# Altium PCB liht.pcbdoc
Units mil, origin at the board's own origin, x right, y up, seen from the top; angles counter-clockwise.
Board outline 7874 x 3937 mil, 2 copper layers (Top Layer, Bottom Layer); 134 components, 84 nets, 415 pads, 109 vias.
Unrouted connection lines stored in the file: 3.
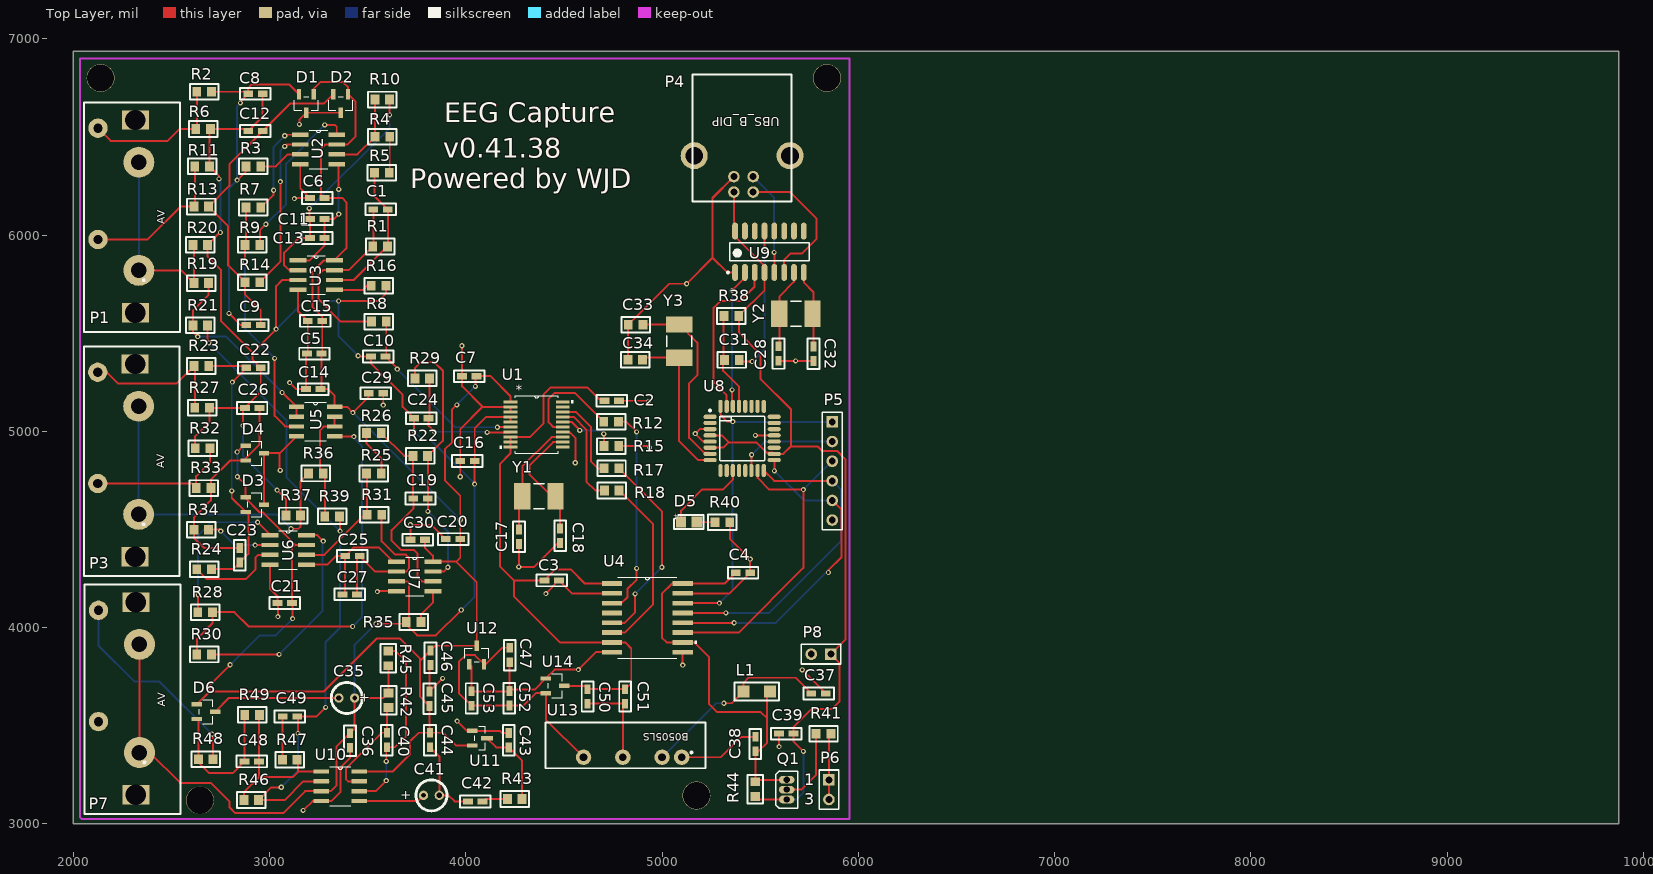
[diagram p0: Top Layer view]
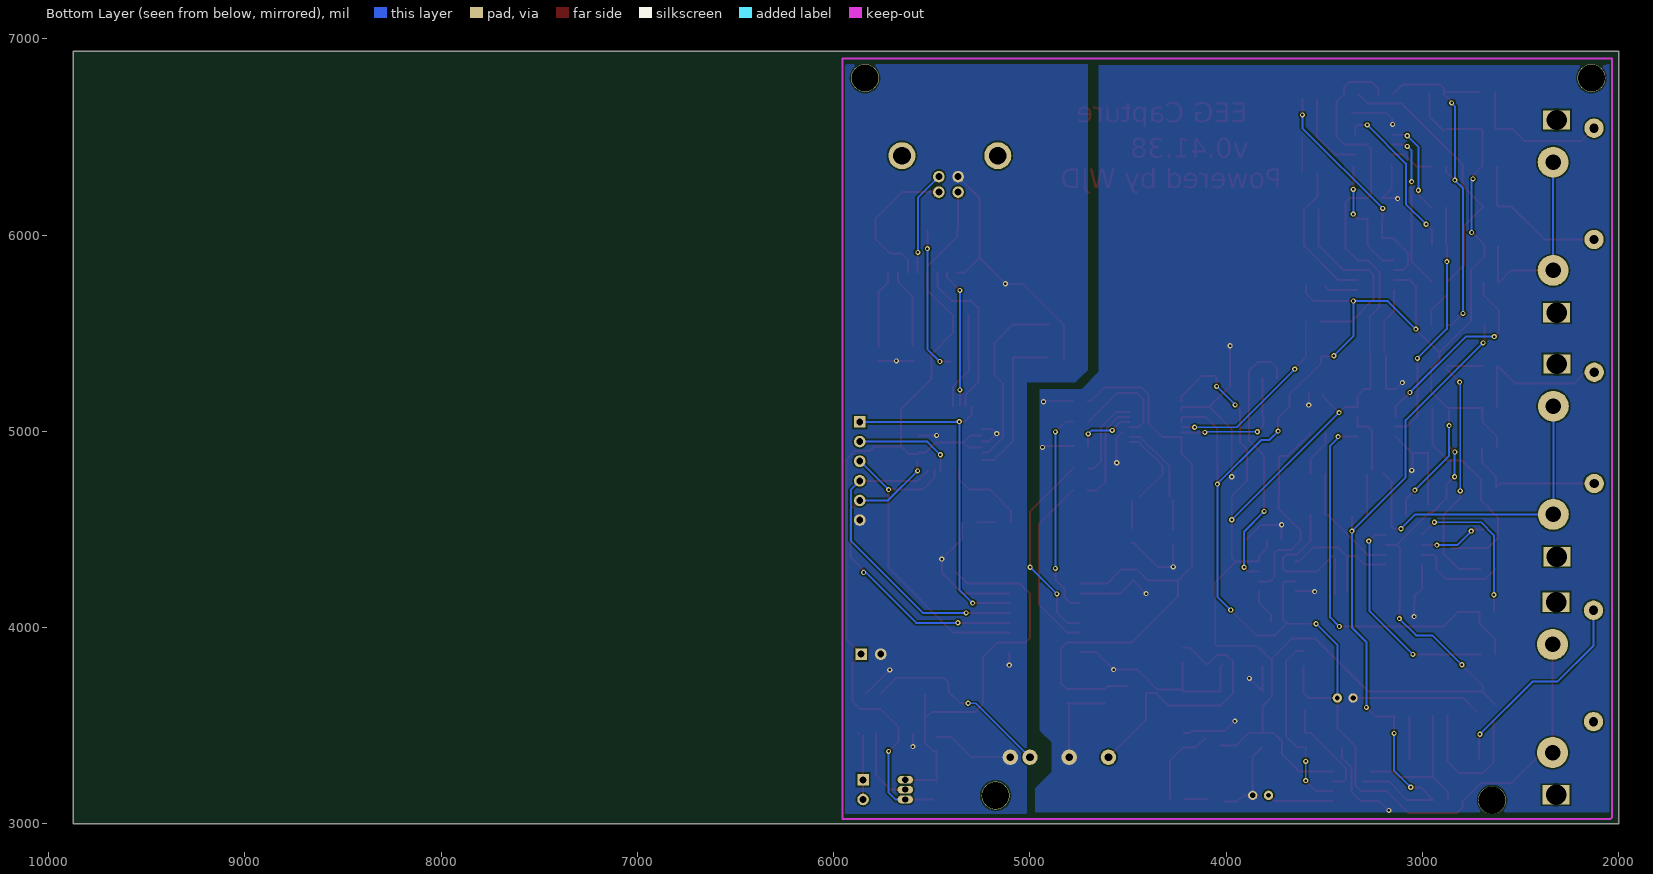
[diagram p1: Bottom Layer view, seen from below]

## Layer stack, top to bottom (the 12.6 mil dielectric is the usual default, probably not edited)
Top Layer: signal copper 1.4
Dielectric: dielectric 12.6, FR-4, Dk 4.8
Bottom Layer: signal copper 1.4

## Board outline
2000,3000 9874,3000 9874,6937 2000,6937

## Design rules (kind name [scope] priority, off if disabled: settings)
Clearance [All] p1: gap=8
PolygonConnect [All] p1: connectstyle=Direct reliefconductorwidth=10 reliefentries=4 polygonreliefangle="90 Angle" airgapwidth=10
RoutingVias [All] p1: holewidth=12 width=24 viastyle="Through Hole" minholewidth=12 minwidth=24 maxholewidth=28 maxwidth=50
SolderMaskExpansion [All] p1: expansion=4
Width [All] p1: maxlimit=10 minlimit=8 preferedwidth=10
28 further rules are at their usual default settings.

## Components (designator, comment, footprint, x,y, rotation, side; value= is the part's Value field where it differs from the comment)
C1 "Cap" 0603 3539,6131 r0 top
C2 "Cap" 0603 4717,5156 r0 top
C3 "Cap" 0603 4465,4241 r180 top
C4 "Cap" 0603 5385,4280 r0 top
C5 "Cap" 0603 3202,5396 r0 top
C6 "Cap" 0603 3216,6189 r0 top
C7 "Cap" 0603 3991,5281 r0 top
C8 "Cap" 0603 2956,6720 r180 top
C9 "Cap" 0603 2946,5541 r180 top
C10 "Cap" 0603 3581,5382 r180 top
C11 "Cap" 0603 3216,6081 r0 top
C12 "Cap" 0603 2956,6530 r180 top
C13 "Cap" 0603 3216,5985 r0 top
C14 "Cap" 0603 3196,5215 r0 top
C15 "Cap" 0603 3205,5563 r0 top
C16 "Cap" 0603 4036,4849 r180 top
C17 "Cap" 0603 4271,4491 r270 top
C18 "Cap" 0603 4481,4495 r270 top
C19 "Cap" 0603 3797,4658 r180 top
C20 "Cap" 0603 3908,4451 r0 top
C21 "Cap" 0603 3051,4126 r0 top
C22 "Cap" 0603 2946,5324 r180 top
C23 "Cap" 0603 2849,4396 r270 top
C24 "Cap" 0603 3801,5067 r180 top
C25 "Cap" 0603 3450,4365 r180 top
C26 "Cap" 0603 2939,5119 r180 top
C27 "Cap" 0603 3436,4170 r180 top
C28 "Cap" 0603 5593,5424 r270 top
C29 "Cap" 0603 3570,5194 r180 top
C30 "Cap" 0603 3728,4448 r0 top
C31 "Cap" 0805 5393,5364 r180 top
C32 "Cap" 0603 5771,5423 r270 top
C33 "Cap" 0805 4828,5543 r0 top
C34 "Cap" 0805 4826,5365 r0 top
C35 "Cap Pol2" 47uf 3394,3642 r180 top
C36 "Cap" 0603 3410,3452 r270 top
C37 "Cap" 0603 5770,3665 r0 top
C38 "Cap" 0603 5475,3380 r90 top
C39 "Cap" 0603 5660,3460 r180 top
C40 "Cap" 0603 3598,3455 r270 top
C41 "Cap Pol2" 47uf 3825,3146 r0 top
C42 "Cap" 0603 4076,3115 r180 top
C43 "Cap" 0603 4219,3400 r90 top
C44 "Cap" 0603 3818,3455 r270 top
C45 "Cap" 0603 3815,3611 r90 top
C46 "Cap" 0603 3820,3874 r270 top
C47 "Cap" 0603 4224,3888 r270 top
C48 "Cap" 0603 2937,3319 r180 top
C49 "Cap" 0603 3132,3547 r180 top
C50 "Cap" 0603 4621,3677 r270 top
C51 "Cap" 0603 4812,3677 r270 top
C52 "Cap" 0603 4222,3614 r90 top
C53 "Cap" 0603 4030,3612 r90 top
D1 "BAV99" SOT23 3188,6670 r180 top
D2 "BAV99" SOT23 3363,6670 r180 top
D3 "BAV99" SOT23 2926,4627 r270 top
D4 "BAV99" SOT23 2926,4889 r270 top
D5 "LED_R" 0805_极性 5137,4538 r0 top
D6 "BAV99" SOT23 2677,3572 r270 top
L1 "Inductor" 1206 5415,3675 r0 top
P1 "Header 3" AV 2335,5820 r90 top
P3 "Header 3" AV 2334,4577 r90 top
P4 "USB" USB_B_DIP 5652,6809 r180 top
P5 "Header 6" HDR1X6 5867,5048 r270 top
P6 "Header 2" HDR1X2 5850,3225 r270 top
P7 "Header 3" AV 2338,3364 r90 top
P8 "Header 2" HDR1X2 5860,3865 r180 top
Q1 "MOSFET-P" E3 5635,3175 r0 top
R1 "Res2" 0805 3526,5942 r0 top
R2 "Res2" 0805 2705,6730 r180 top
R3 "Res2" 0805 2956,6350 r180 top
R4 "Res2" 0805 3613,6501 r180 top
R5 "Res2" 0805 3535,6317 r0 top
R6 "Res2" 0805 2700,6540 r180 top
R7 "Res2" 0805 2956,6140 r180 top
R8 "Res2" 0805 3595,5559 r180 top
R9 "Res2" 0805 2951,5950 r180 top
R10 "Res2" 0805 3537,6690 r0 top
R11 "Res2" 0805 2620,6350 r0 top
R12 "Res2" 0805 4778,5049 r180 top
R13 "Res2" 0805 2690,6145 r180 top
R14 "Res2" 0805 2951,5760 r180 top
R15 "Res2" 0805 4779,4925 r180 top
R16 "Res2" 0805 3519,5742 r0 top
R17 "Res2" 0805 4780,4812 r180 top
R18 "Res2" 0805 4781,4699 r180 top
R19 "Res2" 0805 2690,5755 r180 top
R20 "Res2" 0805 2610,5950 r0 top
R21 "Res2" 0805 2610,5540 r0 top
R22 "Res2" 0805 3806,4875 r180 top
R23 "Res2" 0805 2691,5333 r180 top
R24 "Res2" 0805 2630,4298 r0 top
R25 "Res2" 0805 3570,4785 r180 top
R26 "Res2" 0805 3570,4991 r180 top
R27 "Res2" 0805 2695,5120 r180 top
R28 "Res2" 0805 2635,4079 r0 top
R29 "Res2" 0805 3816,5270 r180 top
R30 "Res2" 0805 2705,3864 r180 top
R31 "Res2" 0805 3497,4575 r0 top
R32 "Res2" 0805 2697,4914 r180 top
R33 "Res2" 0805 2702,4711 r180 top
R34 "Res2" 0805 2690,4499 r180 top
R35 "Res2" 0805 3772,4029 r180 top
R36 "Res2" 0805 3274,4786 r180 top
R37 "Res2" 0805 3159,4571 r180 top
R38 "Res2" 0805 5316,5588 r0 top
R39 "Res2" 0805 3282,4567 r0 top
R40 "Res2" 0805 5270,4537 r0 top
R41 "Res2" 0805 5860,3460 r180 top
R42 "Res2" 0805 3607,3593 r90 top
R43 "Res2" 0805 4287,3127 r180 top
R44 "Res2" 0805 5475,3140 r90 top
R45 "Res2" 0805 3605,3881 r270 top
R46 "Res2" 0805 2945,3122 r180 top
R47 "Res2" 0805 3066,3327 r0 top
R48 "Res2" 0805 2638,3330 r0 top
R49 "Res2" 0805 2949,3556 r180 top
U1 "ADS1255" ADS1255 4361,5035 r0 top
U2 "AD620" AD620 3250,6436 r0 top
U3 "AD8606" AD8606 3238,5796 r0 top
U4 "ADUM1402BRWZ" ADUM1402BRWZ 4925,4050 r0 top
U5 "OPA2335" OPA2335 3235,5050 r0 top
U6 "AD620" AD620 3095,4396 r0 top
U7 "AD8606" AD8606 3740,4261 r0 top
U8 "ATmega328P-AU" TQFP_32_短PIN 5408,4964 r0 top
U9 "CH340G" SOP_16 5547,5915 r90 top
U10 "OPA2335" OPA2335 3361,3192 r0 top
U11 "REF3125AIDBZT" REF3125 4073,3437 r270 top
U12 "MCP1703-5002" SOT23 4056,3861 r0 top
U13 "B1205_0505" B0505LS 5100,3340 r180 top
U14 "MCP1703-3002" SOT23 4455,3704 r270 top
Y1 "8M" XTAL_5023 4373,4669 r180 top
Y2 "XTAL" XTAL_5032_2PIN 5682,5599 r180 top
Y3 "XTAL" XTAL_5032_2PIN 5087,5460 r270 top

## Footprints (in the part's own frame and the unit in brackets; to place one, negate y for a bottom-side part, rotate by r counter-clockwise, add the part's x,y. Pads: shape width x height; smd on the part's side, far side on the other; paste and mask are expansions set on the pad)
47uf [mm]
  round 1.2 hole 0.6: 1(-1.02,0)
  round 1.2 hole 0.7: 2(1.02,0)
  silkscreen extent -2.01,-2.01 2.01,2.01
0603 [mil]
  rect 50x31 smd: 1(-9.84,0) 2(64,0)
  silkscreen extent -50,-30 105,30
0805 [mil]
  rect 45x50 smd: 1(0,0) 2(75,0)
  silkscreen extent -35,-40 110,40
0805_极性 [mm]
  rect 1.35x1.4 smd: 1(-1.025,0) 2(1.025,0)
  silkscreen extent -1.91,-0.89 1.91,0.89, body extent -1,-0.64 1,0.64, height 1.25
1206 [mil]
  rect 60x63 smd: 1(0,0) 2(135,0)
  silkscreen extent -45,-45 180,45
AD620 [mil]
  rect 86x22 smd: 1(-93,75) 2(-93,25) 3(-93,-25) 4(-93,-75) 5(93,-75) 6(93,-25) 7(93,25) 8(93,75)
  silkscreen extent -46,-98 46,98
AD8606 [mil]
  rect 86x22 smd: 1(-93,75) 2(-93,25) 3(-93,-25) 4(-93,-75) 5(93,-75) 6(93,-25) 7(93,25) 8(93,75)
  silkscreen extent -46,-98 46,98
ADS1255 [mil]
  rect 69x15 smd: 1(-133,115.16) 2(-133,89.57) 3(-133,63.98) 4(-133,38.39) 5(-133,12.8) 6(-133,-12.8) 7(-133,-38.39) 8(-133,-63.98) 9(-133,-89.57) 10(-133,-115.16) 11(133,-115.16) 12(133,-89.57) 13(133,-63.98) 14(133,-38.39) 15(133,-12.8) 16(133,12.8) 17(133,38.39) 18(133,63.98) 19(133,89.57) 20(133,115.16)
  silkscreen extent -188,-148 188,148
ADUM1402BRWZ [mil]
  rect 102.5x24 smd: 1(-180.25,175) 2(-180.25,125) 3(-180.25,75) 4(-180.25,25) 5(-180.25,-25) 6(-180.25,-75) 7(-180.25,-125) 8(-180.25,-175) 9(180.25,-175) 10(180.25,-125) 11(180.25,-75) 12(180.25,-25) 13(180.25,25) 14(180.25,75) 15(180.25,125) 16(180.25,175)
  silkscreen extent -150,-206 252,206
AV [mm]
  rect 2.5x3.5 hole 2.64: 0(-5.46,0.457) 0(19.46,0.457)
  round 2.5 hole 1.2: 1(4,5.3) 3(18.4,5.3)
  round 4 hole 2: 2(0,0) 2(14,0)
  silkscreen extent -7.98,-5.31 21.74,7.09
B0505LS [mm]
  round 2 hole 1: 1(0,0) 2(2.54,0) 3(7.62,0) 4(12.7,0)
  silkscreen extent -3.07,-4.5 17.6,1.42
E3 [mm] "TO, Flat Index; 3 In-Line, Axial Leads; Body Dia. 4.6mm; Lead Dia. 0.5 mm (max)"
  oval 2x1 hole 0.8: 1(0,1.27) 2(0,0) 3(0,-1.27)
  silkscreen extent -1.41,-2.41 1.41,2.41
HDR1X2 [mm] "Connector; Header; 2 Position"
  rect 1.5x1.5 hole 0.9: 1(0,0)
  round 1.5 hole 0.9: 2(2.54,0)
  silkscreen extent -1.27,-1.27 3.81,1.27
HDR1X6 [mm] "Connector; Header; 6 Position"
  rect 1.5x1.5 hole 0.9: 1(0,0)
  round 1.5 hole 0.9: 2(2.54,0) 3(5.08,0) 4(7.62,0) 5(10.16,0) 6(12.7,0)
  silkscreen extent -1.27,-1.27 13.97,1.27
OPA2335 [mil]
  rect 78x22 smd: 1(-97,75) 2(-97,25) 3(-97,-25) 4(-97,-75) 5(97,-75) 6(97,-25) 7(97,25) 8(97,75)
  silkscreen extent -54,-98 54,98
REF3125 [mil] "SOP 16"
  rect 22x52 smd: 1(-37.4,-40) 2(37.4,-40)
  rect 22x62.5 smd: 3(0,34.75)
  silkscreen extent -60,-28 60,28
SOP_16 [mm] "SOP 16"
  oval 2.2x0.75 smd: 1(-2.675,4.445) 2(-2.675,3.175) 3(-2.675,1.905) 4(-2.675,0.635) 5(-2.675,-0.635) 6(-2.675,-1.905) 7(-2.675,-3.175) 8(-2.675,-4.445) 9(2.675,-4.445) 10(2.675,-3.175) 11(2.675,-1.905) 12(2.675,-0.635) 13(2.675,0.635) 14(2.675,1.905) 15(2.675,3.175) 16(2.675,4.445)
  silkscreen extent -2.8,-5.15 1.17,5.49, body extent -2.1,-5.15 2.1,5.15, height 1.7
SOT23 [mil]
  rect 22x52 smd: 1(-37.4,-47.06) 2(37.4,-47.06) 3(0,47.06)
  silkscreen extent -61,-35 61,35
TQFP_32_短PIN [mm]
  oval 1.7x0.55 smd: 1(-4.15,2.8) 2(-4.15,2) 3(-4.15,1.2) 4(-4.15,0.4) 5(-4.15,-0.4) 6(-4.15,-1.2) 7(-4.15,-2) 8(-4.15,-2.8) 17(4.15,-2.8) 18(4.15,-2) 19(4.15,-1.2) 20(4.15,-0.4) 21(4.15,0.4) 22(4.15,1.2) 23(4.15,2) 24(4.15,2.8)
  oval 0.55x1.7 smd: 9(-2.8,-4.15) 10(-2,-4.15) 11(-1.2,-4.15) 12(-0.4,-4.15) 13(0.4,-4.15) 14(1.2,-4.15) 15(2,-4.15) 16(2.8,-4.15) 25(2.8,4.15) 26(2,4.15) 27(1.2,4.15) 28(0.4,4.15) 29(-0.4,4.15) 30(-1.2,4.15) 31(-2,4.15) 32(-2.8,4.15)
  silkscreen extent -4.27,-2.9 2.9,3.75, body extent -3.5,-3.5 3.5,3.5, height 1.2
USB_B_DIP [mm]
  round 3.5 hole 2.3: 0(0,10.28) 0(12.4,10.28)
  round 1.5 hole 0.92: 1(7.27,14.99) 2(4.77,14.99) 3(4.77,12.99) 4(7.27,12.99)
  silkscreen extent -0.2,-0.2 12.6,16.21
XTAL_5023 [mm] "5032_CPX_53GB"
  rect 2.1x3.45 smd: 1(-2.15,0) 2(2.15,0)
  silkscreen extent -0.7,-1.63 0.7,1.63, body extent -2.58,-1.68 2.57,1.68, height 1.25
XTAL_5032_2PIN [mm] "5032_CPX_53GB"
  rect 2.1x3.45 smd: 1(-2.15,0) 2(2.15,0)
  silkscreen extent -0.7,-1.63 0.7,1.63, body extent -2.58,-1.68 2.57,1.68, height 1.25

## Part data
C1 C2 C3 C4 C5 C6 C7 C8 C9 C10 C11 C12 C13 C14 C15 C16 C17 C18 C19 C20 C21 C22 C23 C24 C25 C26 C27 C28 C29 C30 C31 C32 C33 C34 C36 C37 C38 C39 C40 C42 C43 C44 C45 C46 C47 C48 C49 C50 C51 C52 C53: "Capacitor"
C35 C41: "Polarized Capacitor (Axial)"
D5: library part LED
P1 P3 P7: "Header, 3-Pin"
P5: "Header, 6-Pin"
P6 P8: "Header, 2-Pin"
Q1: "P-Channel MOSFET"
R38 R40: "Resistor"
U8: "8-bit AVR Microcontroller, 32KB Flash, 1KB EEPROM, 2KB SRAM, 32-pin TQFP, Industrial Grade (-40癈 to 85癈)"
U13: library part B1205/B0505
Y1: library part XTAL, "Crystal Oscillator"
Y2 Y3: "Crystal Oscillator"

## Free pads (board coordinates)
  round 141.73 hole 137.8: 0(5175,3145) 1(2646,3121) 2(5840,6800) 3(2140,6800)

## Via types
v1: diameter 26, hole 13, Top Layer to Bottom Layer, 109 vias

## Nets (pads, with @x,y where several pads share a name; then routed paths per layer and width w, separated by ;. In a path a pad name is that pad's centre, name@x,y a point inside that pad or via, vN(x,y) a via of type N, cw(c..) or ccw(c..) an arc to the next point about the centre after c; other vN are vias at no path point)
+3V: C2.1 C3.2 C50.1 C51.1 U1.8 U1.9 U1.10 U4.1 U4.7 U14.3 | length 3358.8
  Top Layer w10: U14.3 4603.84,3704 C50.1 C51.1 4843,3717.84 4843,3894 4812,3925 U4.7 4480,3925 4245,4160 4245,4241 ; C2.1 4688,5156 4620,5224 4432,5224 4397,5189 4397,5041 4327.02,4971.02 U1.8 U1.9 U1.10 4228,4888 4175,4835 4175,4311 4245,4241 ; U4.1 4606,4225 4534,4297 4457,4297 C3.2 4245,4241
+5V_SW: C4.1 C38.1 L1.2 Q1.1 R44.2 U4.10 U4.16 | length 2119.7
  Top Layer w10: C4.1 5320.16,4225 U4.16 5052,4225 4999,4172 4999,3949 5023,3925 U4.10 5165,3925 5240,3850 5240,3610 5280,3570 5502.5,3570 5535,3537.5 ; R44.2 C38.1 5490.16,3370.16 5535,3415 5535,3537.5 ; R44.2@5485,3225 Q1.1 ; L1.2@5535,3660 5535,3537.5
+5V_USB: C39.1 P4.1 P8.1 Q1.3 R38.2 R44.1 U8.4 U8.6 U8.18 U9.4 U9.16 | length 4533.4
  Top Layer w10: U8.6 5311.76,4916.76 5339.5,4944.5 ; U8.4 5304.25,4979.75 5339.5,4944.5 ; U9.16@5365.78,6026.54 P4.1 ; U9.16 5372,5991 U9.4@5522,5841 ; R44.1@5490,3125 Q1.3 ; U9.4 5522,5719 R38.2 5391,5504 5501,5394 5501,5269 5656,5114 5656,4923 ; v1(5720,3370) 5669.84,3420.16 C39.1 5669.84,3494.84 5760,3585 5865,3585 5905,3625 5905,3820 P8.1 5934,3939 5934,4858 5892,4900 5815,4900 5792,4923 5656,4923 ; 5339.5,4944.5 5340,4944 5479,4944 5530.07,4892.93 5563.72,4892.93 U8.18 5618.26,4885.26 5656,4923
  Bottom Layer w10: Q1.3 5685,3125 5720,3160 v1(5720,3370)
+5VA: C5.2 C6.2 C7.2 C14.2 C15.2 C20.2 C21.2 C29.2 C30.2 C44.1 C45.1 C46.1 D1.1 D2.1 D3.1 D4.1 D6.1 U1.1 U2.7 U3.8 U5.8 U6.7 U7.8 U10.8 U11.2 U12.3 | length 9740.8
  Top Layer w10: D6.1 2695.54,3675 ; v1(2800,3811) 2695.54,3706.54 2695.54,3675 ; v1(2835,4895) D4.1@2866.4,4926.4 ; v1(2837,4769) 2878.94,4727.06 D3.1 2878.94,4659.06 2952,4586 2969,4586 3134,4421 U6.7 ; C21.2 3115,4407 3129,4421 ; v1(3118,4046) C21.2@3118,4123 ; D1.1 3225.4,6744.4 3260,6779 3374,6779 3400.4,6752.6 D2.1 3439,6678.46 3439,6503 3397,6461 U2.7 3284,6461 3262,6439 3262,6207 C6.2 3370,6189 3392,6167 3392,5932 U3.8 3278,5871 3220,5813 3220,5633 3269,5584 C15.2 C5.2@3269,5399 ; C14.2@3266,5215 3299,5215 3332,5182 U5.8 3396,5125 v1(3425,5096) 3506,5177 C29.2 ; C14.2@3266,5217 C5.2 ; U10.8 3627,3267 3716,3356 3716,3421 3759.84,3464.84 C44.1 ; C30.2 3792,4408 3833,4367 U7.8 3952,4336 ; v1(3955,5135) 3929,5109 3929,4943 3894,4908 3894,4750 3972,4672 v1(3972,4550) C20.2 3972,4356 3952,4336 ; U11.2 3951.4,3399.6 3886.16,3464.84 C44.1 ; v1(4049,5229) C7.2@4049,5275 ; C7.2 4127,5281 4228,5180 U1.1 ; 2695.54,3675 3277,3675 3548,3946 3663,3946 3768,3841 3768,3831.84 ; 3768,3831.84 3768,3648.16 C45.1 3815,3467.84 C44.1 ; 3768,3831.84 C46.1 3844.21,3908.06 U12.3 4056,4232 3952,4336
  Bottom Layer w10: v1(2800,3811) 2950,3961 3033,3961 v1(3118,4046) ; v1(2835,4895) 2837,4897 v1(2837,4769) ; v1(3425,5096) 3426,5096 v1(3972,4550) ; v1(3955,5135) v1(4049,5229)
AGND: C8.1 C10.2 C12.2 C16.1 C22.1 C24.2 C26.2 C35.1 C36.1 P7.2 R6.1 R11.2 R16.2 R20.2 R27.1 R32.2 R35.2 R37.2 R42.2 R45.2 U1.4 U1.5 U3.3 U7.3 U10.3 | length 10491
  Top Layer w10: P7.2@2338,3915.18 2338,3364 2390,3364 2545,3209 2701,3209 2797,3113 2797,3084 2824,3057 3072,3057 3182,3167 U10.3 3312,3167 3341,3196 3341,3392.84 C36.1 3434.16,3486 C35.1 3581,3642 R42.2 R45.2@3607,3804 ; R32.2 2622,4975 2695,5048 R27.1 2874,5120 2955.84,5201.84 C22.1 2914.5,5365.34 2914.5,5401.5 ; R6.1@2695,6535 R11.2 2743,6302 v1(2743,6286) ; R6.1 C12.2@2882,6540 ; v1(2750,6013) 2748,6013 R20.2 2685,5890 2754,5821 2754,5562 2914.5,5401.5 ; v1(2865,5029) C26.2@2865,5109 ; C12.2 2965.84,6603.84 C8.1 ; v1(3039,4701) 3084,4656 R37.2 ; U3.3 3065,5771 3034,5740 v1(3034,5521) 2914.5,5401.5 ; v1(3352,5664) 3554,5664 3594,5704 R16.2 ; v1(3452,5385) 3455,5382 C10.2 3517,5348 3679,5186 3679,5125 C24.2 ; v1(3542,4020) 3688,4020 R35.2 ; U7.3 3701,4236 3712,4225 3712,4044 R35.2 ; v1(3736,5001) C24.2@3736,5066 ; v1(3977,4090) 3848,3961 3752,3961 3697,4016 R35.2 ; v1(4045,4731) C16.1@4045,4848.16 ; C16.1 4045.84,5015.84 4103.39,5073.39 U1.4 U1.5
  Bottom Layer w10: v1(2743,6286) 2750,6279 v1(2750,6013) ; v1(2865,5029) 2865,4875 v1(3039,4701) ; v1(3034,5521) 3177,5664 v1(3352,5664) 3352,5485 v1(3452,5385) ; C35.1 3434.16,3912.16 v1(3542,4020) ; v1(3736,5001) 3781,4956 3821.77,4956 4045,4732.77 v1(4045,4731) 4045,4158 v1(3977,4090)
D+: P4.3 U9.5 | length 532.5
  Top Layer w10: v1(5571,5912) 5572,5911 U9.5
  Bottom Layer w10: P4.3 5571,6190.79 v1(5571,5912)
D-: P4.2 U9.6 | length 755
  Top Layer w10: P4.2 5652.16,6218.84 5786,6085 5786,5979 5712,5905 5653,5905 5622,5874 U9.6
DGND: C4.2 C28.2 C32.2 C33.1 C34.1 C37.2 C38.2 C39.2 P4.4 P5.6 P8.2 R40.2 U4.9 U4.15 U8.3 U8.5 U8.21 U9.1 U13.1 | length 3209.8
  Top Layer w10: C34.1 4826,5541 C33.1 5037,5752 v1(5125,5752) 5257,5884 ; U13.1 5300,3340 5404,3444 C38.2 ; v1(5105.25,3809.75) U4.9 ; U4.15 5344,4175 C4.2 v1(5449,4349) 5345,4453 R40.2 ; U8.5 5208.75,4948.25 5169,4988 5192.24,5011.24 U8.3 ; P4.4 5257,6188.8 5257,5884 ; U9.1 5331.31,5809.69 5257,5884 ; v1(5475.75,4979.75) U8.21 ; C28.2@5594,5359 v1(5680,5359) C32.2 ; v1(5596,3394) C39.2 ; v1(5714,3785) C37.2
  other v1: 5169,4989
DIN: P5.3 U4.11 U8.15 | length 1650.1
  Top Layer w10: U4.11 5390,3975 5720,4305 v1(5720,4703) 5547,4703 5486.74,4763.26 U8.15
  Bottom Layer w10: v1(5720,4703) P5.3@5865,4848
DOUT: P5.4 U4.13 U8.16 | length 1654
  Top Layer w10: U4.13 v1(5325,4075) ; U8.16 5570.85,4748 P5.4
  Bottom Layer w10: v1(5325,4075) 5545,4075 5912,4442 5912,4703 P5.4
DRDY: P5.1 U4.14 U8.32 | length 1766.7
  Top Layer w10: U4.14 v1(5292,4125) ; U8.32 5297.76,5085.24 5333,5050 v1(5360,5050)
  Bottom Layer w10: v1(5292,4125) 5360,4193 v1(5360,5050) 5362,5048 P5.1
DTR: C31.1 U9.13 | length 748.4
  Top Layer w10: C31.1@5401,5356 v1(5459,5356) ; v1(5522,5931) U9.13
  Bottom Layer w10: v1(5459,5356) 5522,5419 v1(5522,5931)
GND: C2.2 C3.1 C5.1 C6.1 C7.1 C14.1 C15.1 C16.2 C17.2 C18.2 C20.1 C21.1 C29.1 C30.1 C35.2 C36.2 C41.2 C42.2 C43.2 C44.2 C45.2 C46.2 C47.2 C50.2 C51.2 C52.2 C53.2 D1.3 D2.3 D3.3 D4.3 D6.3 R15.1 U1.2 U1.3 U1.11 U1.14 U2.4 U3.4 U4.2 U4.4 U4.8 U5.4 U6.4 U7.4 U10.4 U11.1 U12.1 U13.3 U14.1 | length 8189.4
  Top Layer w10: D6.3 2794.06,3642 C35.2 ; D3.3 D4.3 3052,4889 ; U6.4 3002,4199 3041.16,4159.84 C21.1 ; v1(3043,4056) C21.1@3043,4124.16 ; v1(3055,4801) 3052,4804 3052,4889 ; v1(3103,5248) 3136,5215 C14.1 C5.1@3186.16,5390 ; v1(3127,6186) 3130,6189 C6.1 3157,6238.16 U2.4 ; U5.4 3052,4889 ; U3.4 3145,5613.16 C15.1 C5.1@3195.16,5399 ; v1(3153,6564) 3153,6587.94 D1.3 D2.3 ; v1(3172,3069) 3220,3117 U10.4 3315,3117 3363,3165 3363,3288 3410,3335 C36.2 ; v1(3550,4184) 3548,4186 U7.4 ; v1(3579.84,5134.16) C29.1 ; C30.1 v1(3718.16,4524.16) 3825,4524.16 C20.1 ; C46.2@3815,3805 C45.2 v1(3882,3742) ; C44.2 3865.16,3343.84 C41.2 3912,3146 3943,3115 C42.2 ; v1(3956,3524) 4005.6,3474.4 U11.1 4173.6,3474.4 4184,3464 C43.2 ; v1(3972,4769) C16.2 3972,5011.13 4085.43,5124.57 ; v1(3980,5436) 3981.16,5434.84 C7.1 3981.16,5228.84 4085.43,5124.57 ; U12.1 4030,3802.54 C53.2 C52.2@4220,3676 ; C52.2 C52.2@4224,3680 ; C47.2 C52.2@4224,3680 ; U1.3 U1.2 4085.43,5124.57 ; C17.2 4271,4311 v1(4270,4310) 4348,4310 4469,4431 C18.2 ; v1(4407.84,4174) C3.1 4540.84,4175 U4.2 ; U1.14@4528.39,4996.61 4533.48,4991.52 4533.88,4991.52 4558,4967.41 v1(4558,4840) ; C50.2 C51.2 ; U4.8 4663,3875 v1(4574,3786) 4452.54,3786 U14.1 4351.14,3684.6 4228.6,3684.6 C52.2@4224,3680 ; R15.1 v1@4936,4925 ; C2.2 v1@4931,5156 ; U13.3 C51.2@4800,3601
  other v1: 4936,4918 4931,5151
LED: D5.1 U8.11 | length 434.7
  Top Layer w10: D5.1 5096.65,4596.65 5203,4703 5310,4703 5360.76,4753.76 U8.11
NetC1_1: C1.1 R1.1 R8.2 U3.7 | length 966.8
  Top Layer w10: R8.2 3364,5559 3251,5672 3251,5798 3274,5821 U3.7 3405,5821 R1.1 3529.16,5945.16 C1.1
NetC1_2: C1.2 R1.2 R5.1 U3.6 | length 742
  Top Layer w10: U3.6 3430,5771 R1.2 ; R5.1 3535,6199 C1.2 R1.2@3603,5944
NetC8_2: C8.2 C9.2 D1.2 R2.1 R3.2 | length 1855.1
  Top Layer w10: R2.1 C8.2@2882,6730 ; v1(2794,5601) 2854,5541 C9.2 ; v1(2835,6280) 2881,6326 R3.2 ; v1(2852,6673) 2852,6680 C8.2 2892,6749 2911,6768 3099.65,6768 D1.2
  Bottom Layer w10: v1(2794,5601) 2794,6239 v1(2835,6280) 2835,6656 v1(2852,6673)
NetC9_1: C9.1 C12.1 D2.2 R13.1 R14.2 | length 1650.6
  Top Layer w10: C9.1 2955.84,5616.16 2876,5696 R14.2 2790,5846 2790,6045 R13.1 2796,6251 2796,6360.16 C12.1 3104.84,6669 3277.54,6669 D2.2
NetC10_1: C10.1 R8.1 U1.6 | length 962.9
  Top Layer w10: C10.1 3651,5321.84 v1(3651,5317) ; C10.1@3595,5386.16 R8.1 ; v1(4161,5021) 4162.2,5022.2 U1.6
  Bottom Layer w10: v1(3651,5317) 3947,5021 v1(4161,5021)
NetC11_1: C11.1 C13.1 R10.2 U3.2 | length 1178.4
  Top Layer w10: U3.2 3100,5821 3075,5846 3075,5911 3149,5985 C13.1 C11.1 ; C11.1@3203,6084.16 v1(3203,6136) ; v1(3612,6612) R10.2
  Bottom Layer w10: v1(3203,6136) 3612,6545 v1(3612,6612)
NetC11_2: C11.2 C13.2 U2.5 U3.1 | length 628.8
  Top Layer w10: U3.1 3205,5871 3280,5946 C13.2 C11.2 3327,6081 v1(3353,6107) ; v1(3353,6233) U2.5@3353,6351
  Bottom Layer w10: v1(3353,6107) v1(3353,6233)
NetC17_1: C17.1 U1.13 Y1.2 | length 571.4
  Top Layer w10: C17.1 Y1.2@4271,4651.65 ; Y1.2 4288.35,4822.35 4437.02,4971.02 U1.13
NetC18_1: C18.1 U1.12 Y1.1 | length 562.9
  Top Layer w10: Y1.1@4437,4669 4324,4782 4324,4824 4445.43,4945.43 U1.12 ; C18.1 Y1.1@4481,4645.65
NetC19_1: C19.1 R22.1 R29.2 U7.7 | length 1385.1
  Top Layer w10: R29.2 3741,5322 3772,5353 3840,5353 3883,5310 3883,4952 R22.1 ; v1(3806.84,4592.16) C19.1 R22.1@3806.84,4874.16 ; U7.7 3887,4286 v1(3909,4308)
  Bottom Layer w10: v1(3806.84,4592.16) 3909,4490 v1(3909,4308)
NetC19_2: C19.2 R22.2 R26.1 U7.6 | length 1050.1
  Top Layer w10: R26.1 3686,4875 R22.2 C19.2@3731,4660 ; C19.2 3733,4607 3623,4497 3623,4443 3671,4395 3737,4395 3755,4377 3755,4258 3777,4236 U7.6
NetC22_2: C22.2 C23.2 D3.2 R23.1 R24.2 | length 1414.2
  Top Layer w10: R23.1 C22.2@2873,5333 ; R24.2 2815,4298 C23.2 2893,4376 2893,4575.54 D3.2 2808,4660.54 v1(2808,4697) ; v1(2811,5251) C22.2@2882,5322
  Bottom Layer w10: v1(2808,4697) 2808,5248 v1(2811,5251)
NetC23_1: C23.1 C26.1 D4.2 R33.1 R34.2 | length 1089.8
  Top Layer w10: C23.1 2668.16,4405.84 2615,4459 R34.2 2615,4561 2702,4648 R33.1 2702,4753 2800.6,4851.6 D4.2 ; D4.2@2878.94,4861.94 2948.84,4931.84 C26.1
NetC24_1: C24.1 R29.1 U1.7 | length 669.4
  Top Layer w10: C24.1 3810.84,5028.16 v1(3841,4998) ; C24.1@3816,5072.16 R29.1 ; v1(4109,4995) 4226.39,4995 U1.7
  Bottom Layer w10: v1(3841,4998) 4108,4998 4109,4997 v1(4109,4995)
NetC25_1: C25.1 C27.1 R31.2 U7.2 | length 835.7
  Top Layer w10: C27.1 C25.1@3445.84,4351 ; C25.1 3538.84,4286 U7.2 3696,4286 3712,4302 3712,4355 3695,4372 3640,4372 3572,4440 R31.2
NetC25_2: C25.2 C27.2 U6.5 U7.1 | length 706.7
  Top Layer w10: U6.5 3294,4321 3338,4365 C25.2 ; C27.2@3386,4184 C25.2 ; U7.1 3630,4336 3557,4409 3430,4409 C25.2
NetC31_2: C31.2 R38.1 U8.29 | length 485.3
  Top Layer w10: C31.2@5311,5361 5311,5308 5392.25,5226.75 U8.29 ; C31.2@5314,5372 R38.1@5314,5590
NetC33_2: C33.2 U8.7 Y3.1 | length 956.4
  Top Layer w10: C33.2@4904.65,5544.65 Y3.1 5180,5451.65 5180,5286 5138,5244 5138,4967.04 5212.11,4892.93 5236.94,4892.93 U8.7
NetC34_2: C34.2 U8.8 Y3.2 | length 798.5
  Top Layer w10: C34.2@4911.35,5375.35 Y3.2 5087,4950 5183.24,4853.76 U8.8
NetC37_1: C37.1 L1.1 U13.2 | length 987.4
  Top Layer w10: v1(5315,3615) 5355,3615 L1.1 5415,3720 5440,3745 5680.16,3745 C37.1
  Bottom Layer w10: U13.2 5275,3615 v1(5315,3615)
NetC40_1: C40.1 R42.1 U10.7 | length 530.3
  Top Layer w10: U10.7 3401,3217 3389,3229 3389,3281 3572.84,3464.84 C40.1 R42.1@3598,3584
NetC40_2: C40.2 R45.1 U10.6 | length 945.8
  Top Layer w10: U10.6 3541,3167 v1(3595,3221) ; v1(3595,3319) 3595,3388 C40.2 3639,3391 3696,3448 3696,3829 3644,3881 R45.1
  Bottom Layer w10: v1(3595,3221) v1(3595,3319)
NetC41_1: C41.1 C42.1 R43.2 U10.5 | length 453
  Top Layer w10: U10.5 3755.84,3117 C41.1 ; C42.1@4097.84,3127 R43.2
NetC43_1: C43.1 R43.1 U11.3 | length 422
  Top Layer w10: U11.3 4154.59,3390.16 C43.1 4287,3322.16 R43.1
NetC47_1: C47.1 C52.1 C53.1 U12.2 U13.4 U14.2 | length 1385.9
  Top Layer w10: C53.1 3965,3667.16 3965,3826 3999.35,3860.35 4047,3860.35 U12.2 4101.94,3813.94 4185.84,3897.84 C47.1 ; C53.1@4032,3604.16 C52.1 4295.16,3604.16 4357.6,3666.6 U14.2 4407.94,3532.06 U13.4
NetC48_1: C48.1 R46.2 R47.2 R49.1 U10.1 | length 847.5
  Top Layer w10: R46.2 2870,3162 2946.84,3238.84 ; R49.1@2946.84,3553.84 C48.1 2946.84,3238.84 ; R47.2@3146,3322 3146,3267 ; U10.1 3146,3267 ; 2946.84,3238.84 3117.84,3238.84 3146,3267
NetC48_2: C48.2 D6.2 R48.1 R49.2 | length 731.2
  Top Layer w10: D6.2@2638,3526.54 R48.1 2638,3314 2693,3259 2813,3259 C48.2 R49.2@2873,3555
NetC49_1: C49.1 R21.2 R39.2 R46.1 U10.2 | length 3424.2
  Top Layer w10: R21.2 2685,5458 v1(2692,5451) ; v1(3060,3187) 3010,3187 R46.1 3077,3122 3172,3217 U10.2 3304,3217 ; C49.1 3239,3547 v1(3286,3594) ; v1(3145,3462) C49.1@3145,3543.84 ; v1(3360,4492) R39.2@3360,4564
  Bottom Layer w10: v1(2692,5451) 3086,5057 3086,4766 v1(3360,4492) 3360,4001 3286,3927 v1(3286,3594) ; v1(3060,3187) 3145,3272 v1(3145,3462)
NetC49_2: C49.2 R47.1 | length 218
  Top Layer w10: R47.1 C49.2@3066,3545
NetD5_2: D5.2 R40.1 | length 91.6
  Top Layer w10: D5.2@5178.35,4537 R40.1
NetP1_1: P1.1 R11.1 R13.2 | length 758.1
  Top Layer w10: P1.1 2379.48,5977.48 2547,6145 R13.2 ; R13.2@2620,6150 R11.1
NetP1_2: P1.2 R19.2 R20.1 | length 1048.1
  Top Layer w10: P1.2@2335,5820 2550,5820 R19.2 R20.1@2615,5945
  Bottom Layer w10: P1.2@2335,5820 P1.2@2335,6371.18
NetP1_3: P1.3 R2.2 R6.2 | length 735.2
  Top Layer w10: P1.3 2190.75,6480 2481,6480 2541,6540 R6.2 ; R6.2@2630,6545 R2.2
NetP3_1: P3.1 R32.1 R33.2 | length 743.4
  Top Layer w10: P3.1 2603.52,4734.48 R33.2 2627,4772 2697,4842 R32.1
NetP3_2: P3.2 R36.2 R37.1 | length 1698.5
  Top Layer w10: v1(3110,4504) 3148,4504 3159,4515 R37.1 3159,4746 R36.2
  Bottom Layer w10: P3.2@2334,5128.18 2334,4577 3037,4577 v1(3110,4504)
NetP3_3: P3.3 R23.2 R27.2 | length 766.8
  Top Layer w10: P3.3 2171.59,5301.41 2230,5243 2526,5243 R23.2 2620,5329 R27.2
NetP6_1: P6.1 P6.2 R41.1 | length 330
  Top Layer w10: P6.2 P6.1 R41.1@5850,3450 ; R41.1@5870,3455 R41.1@5870,3460
NetP7_3: P7.3 R48.2 | length 1074.6
  Top Layer w10: v1(2708,3457) 2713,3452 R48.2
  Bottom Layer w10: P7.3 2129.34,3908.66 2313,3725 2440,3725 v1(2708,3457)
NetQ1_2: Q1.2 R41.2 | length 391.1
  Top Layer w10: Q1.2 5710,3175 5785,3250 R41.2
NetR3_1: R3.1 U2.3 | length 226.3
  Top Layer w10: R3.1 3033,6350 3094,6411 U2.3
NetR4_1: R4.1 R5.2 | length 181
  Top Layer w10: R5.2@3613,6320 R4.1
NetR4_2: R4.2 R10.1 U2.6 | length 421.7
  Top Layer w10: U2.6 3448,6411 R4.2 3538,6689 R10.1
NetR7_1: R7.1 U2.1 | length 497.6
  Top Layer w10: R7.1 3021,6205 v1(3021,6228) ; v1(3078,6506) 3083,6511 U2.1
  Bottom Layer w10: v1(3021,6228) 3021,6449 v1(3078,6506)
NetR7_2: R7.2 R9.2 U5.3 | length 1252.5
  Top Layer w10: v1(2876,5865) R9.2 ; R9.2@2881,5955 R7.2 ; v1(3026,5372) 3026,5079 3080,5025 U5.3
  Bottom Layer w10: v1(2876,5865) 2876,5522 v1(3026,5372)
NetR9_1: R9.1 U2.8 | length 853.2
  Top Layer w10: R9.1 2951,6024 v1(2982,6055) ; v1(3282,6561) 3333,6561 3343,6551 U2.8
  Bottom Layer w10: v1(2982,6055) 3085,6158 3085,6364 v1(3282,6561)
NetR12_1: R12.1 U4.3 | length 1065.7
  Top Layer w10: U4.3 4793,4125 4824,4156 4824,4198 4870,4244 v1(4870,4302) ; R12.1 4818,5049 v1(4870,4997)
  Bottom Layer w10: v1(4870,4302) v1(4870,4997)
NetR12_2: R12.2 U1.15 | length 555.3
  Top Layer w10: U1.15 4445.8,5022.2 4422,5046 4422,5166 4451,5195 4557,5195 R12.2
NetR14_1: R14.1 U2.2 | length 827.3
  Top Layer w10: R14.1 3056,5865 v1(3056,6272) ; v1(3078,6452) 3087,6461 U2.2
  Bottom Layer w10: v1(3056,6272) 3056,6430 v1(3078,6452)
NetR15_2: R15.2 U1.16 | length 297.8
  Top Layer w10: U1.16 4540.2,5047.8 4581,5007 v1(4581,5005) ; v1(4703,4987) 4704,4986 R15.2
  Bottom Layer w10: v1(4581,5005) 4685,5005 v1(4703,4987)
NetR16_1: R16.1 U3.5 | length 175.7
  Top Layer w10: U3.5 3477,5721 R16.1@3498,5742
NetR17_1: R17.1 U4.5 | length 1021.2
  Top Layer w10: U4.5 4810,4025 4863,4078 v1(4863,4172) ; R17.1 4999,4593 v1(4999,4308)
  Bottom Layer w10: v1(4863,4172) v1(4999,4308)
NetR17_2: R17.2 U1.18 | length 431.8
  Top Layer w10: U1.18 4560.02,5098.98 4639,5020 4639,4846 4673,4812 R17.2
NetR18_1: R18.1 U4.6 | length 920.6
  Top Layer w10: U4.6 4810,3975 4954,4119 4954,4526 R18.1
NetR18_2: R18.2 U1.17 | length 521.7
  Top Layer w10: U1.17 4549.61,5073.39 4615,5008 4615,4744 4660,4699 R18.2
NetR19_1: R19.1 R21.1 U5.1 U5.2 | length 1016.8
  Top Layer w10: v1(2635,5483) 2610,5508 R21.1 2610,5615 2690,5695 R19.1 ; v1(3065,5198) U5.1 U5.2
  Bottom Layer w10: v1(2635,5483) 2780,5483 v1(3065,5198)
NetR24_1: R24.1 U6.3 | length 479.6
  Top Layer w10: R24.1 2681,4247 2879,4247 2928,4296 2928,4356 2943,4371 U6.3
NetR25_1: R25.1 R26.2 | length 237.1
  Top Layer w10: R26.2 3495,4937 3570,4862 R25.1
NetR25_2: R25.2 R31.1 U6.6 | length 588.5
  Top Layer w10: U6.6 3280,4371 R31.1@3484,4575 ; R31.1 R25.2@3497,4783
NetR28_1: R28.1 U6.1 | length 811.4
  Top Layer w10: R28.1 2635,4166 v1(2637,4168) ; v1(2940,4537) U6.1@3002,4475
  Bottom Layer w10: v1(2637,4168) 2637,4472 2702,4537 v1(2940,4537)
NetR28_2: R28.2 R30.2 U5.5 | length 2091.8
  Top Layer w10: R30.2 2630,3942 2710,4022 R28.2 2821,4079 2894,4006 v1(3424,4006) ; U5.5@3334,4973 v1(3430,4973)
  Bottom Layer w10: v1(3424,4006) 3471,4053 3471,4926 3430,4967 v1(3430,4973)
NetR30_1: R30.1 U6.8 | length 1112.6
  Top Layer w10: R30.1 v1(3049,3864) ; U6.8 3244,4471 v1(3274,4441)
  Bottom Layer w10: v1(3049,3864) 3271,4086 3271,4438 v1(3274,4441)
NetR34_1: R34.1 U6.2 | length 344.3
  Top Layer w10: R34.1 2745,4499 v1(2752,4492) ; v1(2927,4421) U6.2
  Bottom Layer w10: v1(2752,4492) 2823,4421 v1(2927,4421)
NetR35_1: R35.1 U7.5 | length 182.3
  Top Layer w10: R35.1 3772,4066 3833,4127 U7.5
NetR36_1: R36.1 R39.1 U5.6 U5.7 | length 546.3
  Top Layer w10: R36.1@3258,4802 3258,5005 3278,5025 U5.6 U5.7 ; R39.1 R36.1@3282,4778
RX: U8.30 U9.2 | length 705.5
  Top Layer w10: U8.30@5357,5131.14 v1(5357,5211) ; v1(5357,5718) 5422,5783 U9.2
  Bottom Layer w10: v1(5357,5211) v1(5357,5718)
SCLK: P5.5 U4.12 U8.17 | length 1690.1
  Top Layer w10: U4.12 v1(5367,4025) ; v1(5572,4799) U8.17@5572,4853.15 ; v1(5847,4281) 5847,4292 5915,4360 5915,4600 P5.5
  Bottom Layer w10: v1(5367,4025) 5580,4025 5847,4292 v1(5847,4281) ; v1(5572,4799) 5723,4648 P5.5
SS: P5.2 U8.14 | length 518.4
  Top Layer w10: U8.14@5456,4801.37 v1(5456,4881)
  Bottom Layer w10: v1(5456,4881) 5523,4948 P5.2
TX: U8.31 U9.3 | length 855.5
  Top Layer w10: U8.31 5329.26,5183.74 5263,5250 5263,5630 5298,5665 5399,5665 5472,5738 U9.3
XI: C28.1 U9.7 Y2.2 | length 402.4
  Top Layer w10: C28.1@5597.35,5438.2 Y2.2 5597.35,5686.35 5672,5761 U9.7
XO: C32.1 U9.8 Y2.1 | length 397.1
  Top Layer w10: U9.8 5722,5759 5771,5710 C32.1
pads on no net: P1.0 P3.0 P4.0 P7.0 P7.1 U1.19 U1.20 U8.1 U8.2 U8.9 U8.10 U8.12 U8.13 U8.19 U8.20 U8.22 U8.23 U8.24 U8.25 U8.26 U8.27 U8.28 U9.9 U9.10 U9.11 U9.12 U9.14 U9.15

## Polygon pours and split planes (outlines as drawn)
GND on Bottom Layer "Bottom Layer-No Net" (solid, pour order 7): 2045,6886 2067,6864 4649,6864 4649,5303 4734,5218 4738,5214 4951,5214 4951,3477 4942,3468 4890,3416 4890,3309 4890,3266 4971,3185 4974,3182 4974,3060 2051,3060 2043,3052
DGND on Bottom Layer "Bottom Layer-No Net" (solid, pour order 5): 4706,6869 4706,5312 4740,5278 4768,5250 5017,5250 5017,3047 5022,3052 5941,3052 5941,6863 5935,6869

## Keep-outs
Keep-Out Layer:
  lines w10: 2035,3035 2045,3025 5955,3025 5955,6900 2035,6900 2035,3035

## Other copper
Top Layer:
  text "EEG Capture" at 3891,6575 h100
  text "v0.41.38" at 3886,6393 h100
  text "Powered by WJD" at 3718,6239 h100

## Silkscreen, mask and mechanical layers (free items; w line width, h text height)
Top Overlay:
  text "EEG Capture" at 3891,6575 h100
  text "v0.41.38" at 3886,6393 h100
  text "Powered by WJD" at 3718,6239 h100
